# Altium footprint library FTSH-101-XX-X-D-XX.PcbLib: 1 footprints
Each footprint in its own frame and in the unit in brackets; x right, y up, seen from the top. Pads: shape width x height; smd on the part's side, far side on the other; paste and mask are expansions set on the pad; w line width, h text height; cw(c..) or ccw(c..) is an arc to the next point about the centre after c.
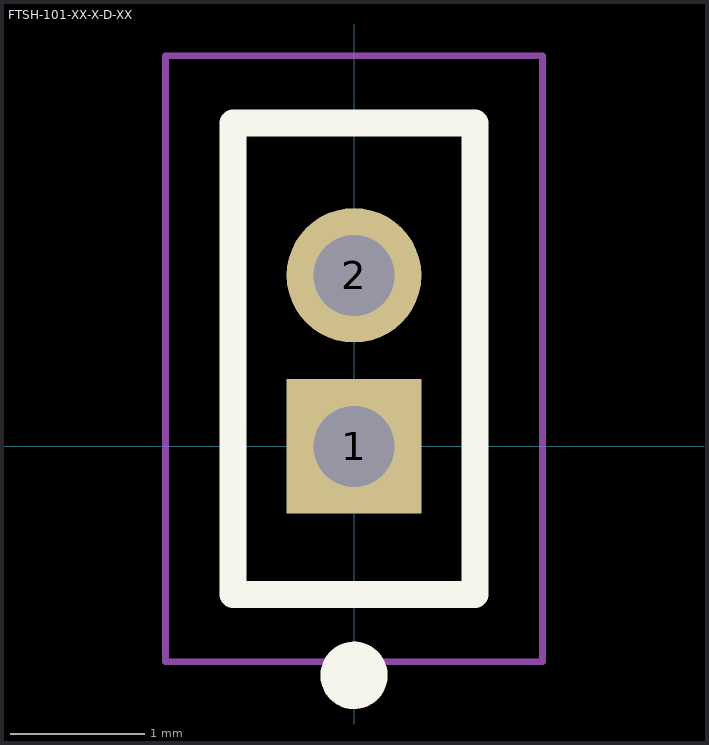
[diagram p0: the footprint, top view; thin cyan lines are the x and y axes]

## FTSH-101-XX-X-D-XX [mm] "1.27mm pitch, 2 pin, interconnect strip; double row"
height 3.05
pads (2):
  rect 1x1 / inner round 1 / far side rect 1x1 hole 0.6 mask+0: 1(0,0)
  round 1 hole 0.6 mask+0: 2(0,1.27)
Top Overlay:
  circle w0.25: c0,-1.7 r0.125
  lines w0.2: -0.9,-1.1 0.9,-1.1 0.9,2.4 -0.9,2.4 -0.9,-1.1
Mechanical 12:
  lines w0.001: -0.9,-1.1 0.9,-1.1 0.9,2.4 -0.9,2.4 -0.9,-1.1
Mechanical 13:
  lines w0.1: -0.9,-1.1 0.9,-1.1 0.9,2.4 -0.9,2.4 -0.9,-1.1
  text ".Designator" at 0.254,0.254 h1.52
Mechanical 15:
  lines w0.05: -1.4,-1.6 1.4,-1.6 1.4,2.9 -1.4,2.9 -1.4,-1.6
